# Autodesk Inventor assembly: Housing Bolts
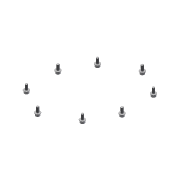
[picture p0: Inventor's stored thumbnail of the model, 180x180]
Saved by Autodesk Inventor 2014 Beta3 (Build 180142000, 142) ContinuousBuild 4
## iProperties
Created: 2011-01
Part Number: Housing Bolts
Document SubType Name: Assembly
Designer: Beta-8540w
ClientObjectVersion: 1
Author: Beta-8540w
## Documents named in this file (3)
- C:\Inventor 2014 Essentials\Assemblies\Chapter 09\Design Accelerators\Bolted Connection c09-01.iam
- C:\Inventor 2014 Essentials\Content Center Files\en-US\ISO 7089\ISO 7089 - 4 - 140 HV.ipt
- C:\Inventor 2014 Essentials\Content Center Files\en-US\ISO 4762\ISO 4762 - M4 x 10ISO.ipt
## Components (16 placed, 2 different names)
1. ISO 7089 4 - 140 HV:1
2. ISO 4762 M4 x 10:1
3. ISO 4762 M4 x 10:2
4. ISO 4762 M4 x 10:3
5. ISO 4762 M4 x 10:4
6. ISO 4762 M4 x 10:5
7. ISO 4762 M4 x 10:6
8. ISO 4762 M4 x 10:7
9. ISO 4762 M4 x 10:8
10. ISO 7089 4 - 140 HV:2
11. ISO 7089 4 - 140 HV:3
12. ISO 7089 4 - 140 HV:4
13. ISO 7089 4 - 140 HV:5
14. ISO 7089 4 - 140 HV:6
15. ISO 7089 4 - 140 HV:7
16. ISO 7089 4 - 140 HV:8
